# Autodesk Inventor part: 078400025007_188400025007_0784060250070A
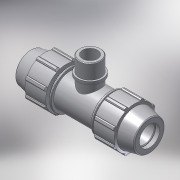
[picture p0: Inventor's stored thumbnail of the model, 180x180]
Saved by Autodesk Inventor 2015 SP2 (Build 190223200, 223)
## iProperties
Created: 2017-02
Part Number: 078400025007_188400025007_0784060250070A
Material: PVC-Piping
Description: PLASSON TEE WITH THREADED MALE OFFTAKE 25-3/4"-25
Document SubType Name: Modeling
Designer: KIM
Mass: 92.6774 g
Surface Area: 199.44 cm^2
Volume: 66.1981 cm^3
Density: 1.4 g/cm^3
Appearance: Smooth - White
Author: Кирилл
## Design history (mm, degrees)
derived "07840.ipt"
feature "Solid1::07840.ipt"
feature "Solid2::07840.ipt"
tag "TaggingFeature1"
body "Solid1"
body "Solid2"
other parameters: "d2" = 25, "d4" = 6.08333, "d5" = 17.52, "d7" = 54, "d11" = 2.43333, "d13" = 120 deg, "d14" = 37.5, "d15" = 12 deg, "d16" = 46.98, "d18" = 1.25, "d19" = 35 deg, "d20" = 17.5 deg, "d21" = 50.22, "d23" = 0, "d25" = 360 deg, "d27" = 1.08, "d33" = 0.5, "d42" = 26.28, "d43" = 1.62, "d46" = 0.75, "d68" = 2.43333, "d73" = 26.441, "d74" = 18, "d75" = 30.40715, "d76" = 18.5087, "d77" = 21.6, "d80" = 0.79323, "d91" = 40.5, "d93" = 58, "d95" = 22.5, "d99" = 146, "d101" = 0, "d103" = 0, "d105" = 0, "d_" = 25, "E_" = 54, "l_" = 58, "l_2" = 18, "H_" = 146, "R_" = 26.441
